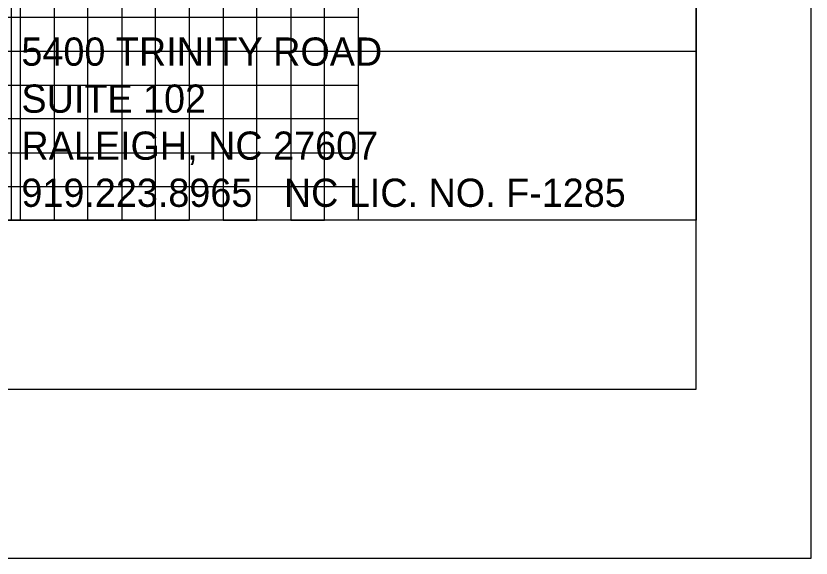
# Model space of a CAD drawing. Extents: x 1524869 to 1526553, y 501099 to 502199.
# Drawn here: x 1526435.4 to 1526553.1, y 501098.6 to 501178.8 of the extents above; entities that cross this region are included whole.
import ezdxf

# ---------------------------------------------------------------- set-up
doc = ezdxf.new("R2010")
doc.units = 0
for name, color, linetype in [('Prop Grid Mask', 7, 'Continuous'), ('Prop Horizontal Alignment Curve and Spiral Data', 7, 'Continuous'), ('Sheet Layout Profile Border Port 2', 7, 'Continuous'), ('Sheet Plot Border Outside CELL', 7, 'Continuous'), ('Sheet Profile CELL', 7, 'Continuous'), ('Sheet Profile Grid Major CELL', 7, 'Continuous'), ('Sheet Profile Grid Middle CELL', 7, 'Continuous'), ('Sheet Profile Grid Minor CELL', 7, 'Continuous')]:
    doc.layers.add(name, color=color, linetype=linetype)

msp = doc.modelspace()

# ---------------------------------------------------------------- linework, layer by layer
at = {"layer": 'Prop Grid Mask'}
msp.add_lwpolyline([(1526434.75, 501200.68), (1526536.08, 501200.68), (1526536.08, 501148.56), (1526434.75, 501148.56)], close=True, dxfattribs=at)
at = {"layer": 'Sheet Layout Profile Border Port 2'}
msp.add_lwpolyline([(1525086.08, 501648.56), (1526486.08, 501648.56), (1526486.08, 501148.56), (1525086.08, 501148.56)], close=True, dxfattribs=at)
at = {"layer": 'Sheet Plot Border Outside CELL'}
msp.add_lwpolyline([(1524869.08, 501098.56), (1526553.08, 501098.56), (1526553.08, 502198.56), (1524869.08, 502198.56)], close=True, dxfattribs=at)
at = {"layer": 'Sheet Profile CELL'}
for p, q in [((1526536.08, 501148.56), (1525036.08, 501148.56)), ((1525036.08, 501123.56), (1526536.08, 501123.56))]:
    msp.add_line(p, q, dxfattribs=at)
msp.add_lwpolyline([(1526536.08, 502173.56), (1525036.08, 502173.56), (1525036.08, 501123.56), (1526536.08, 501123.56)], close=True, dxfattribs=at)
at = {"layer": 'Sheet Profile Grid Major CELL'}
msp.add_line((1526436.08, 501148.56), (1526436.08, 501148.56), dxfattribs=at)
msp.add_line((1526436.08, 501148.56), (1526436.08, 501148.56), dxfattribs=at)
msp.add_line((1526436.08, 501148.56), (1526436.08, 501148.56), dxfattribs=at)
msp.add_line((1526436.08, 501148.56), (1526436.08, 501148.56), dxfattribs=at)
msp.add_line((1526436.08, 501148.56), (1526436.08, 501148.56), dxfattribs=at)
msp.add_line((1526436.08, 501148.56), (1526436.08, 501148.56), dxfattribs=at)
msp.add_line((1526436.08, 501148.56), (1526436.08, 501148.56), dxfattribs=at)
for points in [[(1525986.08, 501148.56), (1526036.08, 501148.56), (1526036.08, 501648.56), (1526086.08, 501648.56), (1526086.08, 501148.56), (1526136.08, 501148.56), (1526136.08, 501648.56), (1526186.08, 501648.56), (1526186.08, 501148.56), (1526236.08, 501148.56), (1526236.08, 501648.56), (1526286.08, 501648.56), (1526286.08, 501148.56), (1526336.08, 501148.56), (1526336.08, 501648.56), (1526386.08, 501648.56), (1526386.08, 501148.56), (1526436.08, 501148.56), (1526436.08, 501148.56), (1526436.08, 501648.56), (1526486.08, 501648.56), (1526486.08, 501148.56)], [(1526536.08, 501148.56), (1525036.08, 501148.56)]]:
    msp.add_lwpolyline(points, dxfattribs=at)
at = {"layer": 'Sheet Profile Grid Middle CELL'}
for points in [[(1526011.08, 501148.56), (1526061.08, 501148.56), (1526061.08, 501648.56), (1526111.08, 501648.56), (1526111.08, 501148.56), (1526161.08, 501148.56), (1526161.08, 501648.56), (1526211.08, 501648.56), (1526211.08, 501148.56), (1526261.08, 501148.56), (1526261.08, 501648.56), (1526311.08, 501648.56), (1526311.08, 501148.56), (1526361.08, 501148.56), (1526361.08, 501648.56), (1526411.08, 501648.56), (1526411.08, 501148.56), (1526461.08, 501148.56), (1526461.08, 501648.56)], [(1526536.08, 501173.56), (1525036.08, 501173.56)]]:
    msp.add_lwpolyline(points, dxfattribs=at)
at = {"layer": 'Sheet Profile Grid Minor CELL'}
for p, q in [((1526486.08, 501178.56), (1525086.08, 501178.56)), ((1525086.08, 501168.56), (1526486.08, 501168.56)), ((1526486.08, 501163.56), (1525086.08, 501163.56)), ((1525086.08, 501158.56), (1526486.08, 501158.56)), ((1525086.08, 501153.56), (1526486.08, 501153.56)), ((1526486.08, 501153.56), (1526486.08, 501153.56)), ((1526486.08, 501153.56), (1526486.08, 501153.56)), ((1526486.08, 501153.56), (1526486.08, 501153.56)), ((1526486.08, 501153.56), (1526486.08, 501153.56)), ((1526486.08, 501153.56), (1526486.08, 501153.56)), ((1526486.08, 501153.56), (1526486.08, 501153.56)), ((1526486.08, 501153.56), (1526486.08, 501153.56))]:
    msp.add_line(p, q, dxfattribs=at)
for points in [[(1526441.08, 501648.56), (1526441.08, 501148.56), (1526446.08, 501148.56), (1526446.08, 501648.56)], [(1526451.08, 501648.56), (1526451.08, 501148.56), (1526456.08, 501148.56), (1526456.08, 501648.56)], [(1526466.08, 501648.56), (1526466.08, 501148.56), (1526471.08, 501148.56), (1526471.08, 501648.56)], [(1526476.08, 501648.56), (1526476.08, 501148.56), (1526481.08, 501148.56), (1526481.08, 501648.56)]]:
    msp.add_lwpolyline(points, dxfattribs=at)

# ---------------------------------------------------------------- texts
at = {"layer": 'Prop Horizontal Alignment Curve and Spiral Data'}
for s, height, p in [('5400 TRINITY ROAD', 4.1773, (1526436.23, 501171.44)), ('SUITE 102', 4.177, (1526436.23, 501164.48)), ('RALEIGH, NC 27607', 4.1773, (1526436.23, 501157.52)), ('919.223.8965   NC LIC. NO. F-1285', 4.1773, (1526436.23, 501150.55))]:
    msp.add_text(s, height=height, rotation=360, dxfattribs=at).set_placement(p)

doc.saveas('drawing.dxf')
